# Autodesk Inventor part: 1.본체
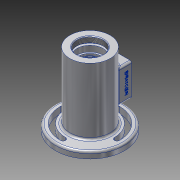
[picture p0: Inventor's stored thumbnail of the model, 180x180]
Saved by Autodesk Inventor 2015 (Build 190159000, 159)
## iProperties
Created: 2017-05
Part Number: 1.본체
Material: 알루미늄 6061
Document SubType Name: Modeling
Designer: user
Density: 2.7 g/cm^3
Appearance: 알루미늄 - 평지
Mass: 679.773 g
Surface Area: 617.525 cm^2
Volume: 251.768 cm^3
Author: user
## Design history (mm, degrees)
sketch "스케치1"
  geometry: C1 r 31 at (0, 0); 1 further point
  constraints: 1 centre point, 1 coincident
  dimensions: "d0" = 62 diameter of C1
extrude "돌출1" new body sketch "스케치1" distance "d1" = 102; taper "d2" = 0 deg
sketch "스케치2"
  geometry: C1 r 53 at (0, 0); 1 further point
  constraints: 1 centre point, 1 coincident
  dimensions: "d3" = 106 diameter of C1
extrude "돌출2" join sketch "스케치2" distance "d4" = 10; taper "d5" = 0 deg
sketch "스케치3"
  geometry: C1 r 31 at (0, 0); 1 further point
  constraints: 1 centre point, 1 coincident
  dimensions: "d6" = 62 diameter of C1
extrude "돌출3" join sketch "스케치3" distance "d7" = 3; taper "d8" = 0 deg
hole "구멍1" diameter "d11" = 40.376; stored, may be unused: countersink angle "d15" = 90 deg, drill point angle "d17" = 0 deg; dims "d12" = 9, "d13" = 4, "d14" = 2, "d16" = 9, "d18" = 10, "d19" = 10
node "작업 평면1"
sketch "스케치4"
  geometry: L1 (-20, -31)-(20, -31); L2 (20, -31)-(20, -81); L3 (20, -81)-(-20, -81); L4 (-20, -81)-(-20, -31); L5 (-20, -31)-(20, -81); L6 (20, -31)-(-20, -81); L7 (-31, 0)-(31, 0) reference; L8 (-31, -102)-(31, -102) reference; L9 (-31, 0)-(31, 0) reference; 2 further points
  constraints: 12 end point, 2 midpoint, 2 parallel, 1 horizontal, 1 perpendicular
  dimensions: "d21" = 56 distance from line of L7 point (0, -56); "d22" = 50 distance of L3.end L1.start; "d23" = 40 distance of L2.end L3.end; "d24" = 31 horizontal distance of L7.end point (0, -56)
extrude "돌출4" join sketch "스케치4" stored distance "d25" = 3; taper "d26" = 0 deg
sketch "스케치5"
  geometry: L1 (-31, 0)-(31, 0) reference; L2 (-31, -115)-(31, -115) reference; L3 (0, -9)-(0, -115); L4 (20.188, -9)-(-20.188, -9) reference; L5 (0, -9)-(24, -9); L6 (24, -9)-(24, -12); L7 (24, -12)-(20, -12); L8 (20, -12)-(20, -21); L9 (20, -21)-(17.5, -21); L10 (17.5, -21)-(17.5, -24.25); L11 (17.5, -24.25)-(18.5, -24.25); L12 (18.5, -26)-(17.5, -26); L13 (17.5, -26)-(17.5, -37); L14 (17.5, -37)-(26, -37); L15 (26, -37)-(26, -75); L16 (26, -75)-(17.5, -75); L17 (17.5, -75)-(17.5, -86); L18 (17.5, -86)-(16.5, -86); L19 (16.5, -86)-(16.5, -91); L20 (16.5, -91)-(10, -91); L21 (10, -91)-(10, -93.7); L22 (10, -93.7)-(12.5, -93.7); L23 (22, -115)-(0, -115); L24 (18.5, -24.25)-(18.5, -26); L25 (12.5, -93.7)-(12.5, -100.3); L26 (12.5, -100.3)-(12.904, -101); L27 (12.904, -101)-(16, -101); L28 (16, -101)-(22, -115); 1 further point
  constraints: 50 end point, 15 perpendicular, 3 collinear, 3 vertical, 2 midpoint, 2 point on line, 1 horizontal
  dimensions: "d27" = 48 diameter of L6 L3; "d28" = 3 distance of L5.end L6.end; "d29" = 40 diameter of L8 L3; "d30" = 21 distance from line of L1 L9.end; "d31" = 35 diameter of L10 L3; "d34" = 37 diameter of L24 L3; "d35" = 1.75 distance of L11.end L12.start; "d36" = 26 distance between parallel lines of L1 L12; "d37" = 38 distance of L14.end L15.end; "d38" = 52 diameter of L15 L3; "d39" = 33 diameter of L19 L3; "d40" = 20 diameter of L21 L3; "d42" = 2.7 distance of L20.end L21.end; "d43" = 25 diameter of L25 L3; "d44" = 7.3 distance from line of L26.end L22; "d45" = 0.7 vertical distance of L26.end L25.end; "d46" = 30 deg angle of L25 L26; "d47" = 32 diameter of L27.end L3; "d48" = 44 diameter of L23.start L3; "d49" = 11 distance of L16.end L17.end; "d50" = 60 distance between parallel lines of L18 L12; "d51" = 14 distance between parallel lines of L2 L27
revolve "회전1" sketch "스케치5" stored, may be unused: angle "d52" = 90 deg
sketch "스케치7"
  geometry: L1 (11, 40)-(-11, 40); L2 (-11, 40)-(-11, 72); L3 (-11, 72)-(11, 72); L4 (11, 72)-(11, 40); L5 (11, 40)-(-11, 72); L6 (-11, 40)-(11, 72); L7 (20, 31)-(-20, 31) reference; L8 (-20, 31)-(-20, 81) reference; 2 further points
  constraints: 12 end point, 2 midpoint, 2 parallel, 1 horizontal, 1 perpendicular
  dimensions: "d53" = 32 distance of L1.end L2.end; "d54" = 22 distance of L1.start L1.end; "d55" = 9 distance between parallel lines of L7 L1; "d56" = 9 distance between parallel lines of L8 L2
extrude "돌출5" cut sketch "스케치7" stored distance "d57" = 3; taper "d58" = 0 deg
sketch "스케치8"
  geometry: L1 (20, 31)-(-20, 31) reference; L2 (-20, 31)-(-20, 81) reference; 2 further points
  dimensions: "d59" = 4.5 distance from line of L1 point (-15.5, 35.5); "d60" = 4.5 distance from line of L2 point (-15.5, 35.5)
hole "구멍2" sketch "스케치8" at (-15.5, 35.5) diameter "d61" = 2.459; stored, may be unused: countersink angle "d65" = 90 deg, drill point angle "d67" = 118 deg; dims "d62" = 6, "d63" = 4, "d64" = 2, "d66" = 8
sketch "스케치9"
  geometry: L1 (0, 0)-(-53, 0); L2 (0, 0)-(0, 53); L3 (29.345, 29.345)-(-29.345, -29.345); A1 r 41.5 centre (0, 0) between (0, 41.5) and (29.345, 29.345); A2 r 41.5 centre (0, 0) between (0, 41.5) and (-41.5, 0); A3 r 45.5 centre (0, 0) between (0, 45.5) and (-45.5, 0); A4 r 37.5 centre (0, 0) between (0, 37.5) and (-37.5, 0); A5 r 4 centre (0, 41.5) between (0, 37.5) and (0, 45.5); A6 r 4 centre (-41.5, 0) between (-45.5, 0) and (-37.5, 0); A7 r 53 centre (0, 0) between (-53, 0) and (0, 53) reference; A8 r 4 centre (41.5, 0) between (45.5, 0) and (37.5, 0); A9 r 45.5 centre (0, 0) between (0, -45.5) and (45.5, 0); A10 r 37.5 centre (0, 0) between (0, -37.5) and (37.5, 0); A11 r 4 centre (0, -41.5) between (0, -37.5) and (0, -45.5); 2 further points
  constraints: 23 point on circle, 10 centre point, 6 end point, 6 symmetric about line, 4 tangent, 3 coincident, 2 point on line, 1 concentric, 1 horizontal, 1 midpoint, 1 perpendicular, 4 other
  dimensions: "d74" = 83 diameter of A1; "d75" = 4 radius of A5; "d76" = 45 deg angle of L2 L3
extrude "돌출6" cut sketch "스케치9" stored distance "d77" = 3; taper "d78" = 0 deg
node "작업 평면2"
sketch "스케치10"
  geometry: L1 (50, 0)-(0, 0) reference; L2 (-31, -75)-(-31, -13) reference; 2 further points
  constraints: 1 other
  dimensions: "d80" = 8 distance from line of L1 point (25, -8); "d81" = 56 distance from line of L2 point (25, -8)
feature "엠보싱1" sketch "스케치10" dims "d82" = 0.5, "d83" = 0
chamfer "모따기1" distance "d84" = 1; stored, may be unused: second distance "d85" = 2, angle "d86" = 45 deg
fillet "모깎기1" dims "d87" = 3
chamfer "모따기2" distance "d89" = 1; stored, may be unused: second distance "d90" = 2, angle "d91" = 45 deg
fillet "모깎기4" dims "d93" = 3
fillet "모깎기5" dims "d94" = 0.3
fillet "모깎기6" dims "d95" = 3
chamfer "모따기3" distance "d96" = 1; stored, may be unused: second distance "d97" = 2, angle "d98" = 45 deg
fillet "모깎기7" dims "d99" = 3
fillet "모깎기8" dims "d100" = 3
fillet "모깎기9" dims "d101" = 0.3
node "솔리드1"
pattern_linear "직사각형 패턴1" dims "d70" = 41, "d73" = 31
node "투영된 루프1"
other parameters: "d20" = 44, "d79" = 5
